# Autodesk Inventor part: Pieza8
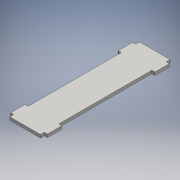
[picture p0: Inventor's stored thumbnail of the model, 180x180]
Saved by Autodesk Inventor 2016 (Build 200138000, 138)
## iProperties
Created: 2016-06
Part Number: Pieza8
Material: Genérico
Document SubType Name: Modeling
Designer: adm
Density: 1 g/cm^3
Appearance: Valor por defecto
Author: adm
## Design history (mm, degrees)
sketch "Boceto1"
  geometry: L1 (29.5, -125)-(-29.5, -125); L2 (-29.5, 125)-(29.5, 125); L3 (29.5, -125)-(-29.5, 125); L4 (-29.5, -125)-(29.5, 125); L5 (29.5, 117.561)-(35.5, 117.561); L6 (35.5, 117.561)-(35.5, 89.561); L7 (35.5, 89.561)-(29.5, 89.561); L8 (0, 0)-(-55.304, 0); L9 (0, 0)-(0, -42.823); L10 (-29.5, 117.561)-(-35.5, 117.561); L11 (-35.5, 117.561)-(-35.5, 89.561); L12 (-35.5, 89.561)-(-29.5, 89.561); L13 (35.5, -89.56)-(29.5, -89.56); L14 (35.5, -117.56)-(35.5, -89.56); L15 (29.5, -117.56)-(35.5, -117.56); L16 (-35.5, -89.561)-(-29.5, -89.561); L17 (-29.5, -117.561)-(-35.5, -117.561); L18 (-35.5, -117.561)-(-35.5, -89.561); L19 (29.5, -117.56)-(29.5, -125); L20 (-29.5, -125)-(-29.5, -117.561); L21 (-29.5, -89.561)-(-29.5, 89.561); L22 (-29.5, 117.561)-(-29.5, 125); L23 (29.5, 125)-(29.5, 117.561); L24 (29.5, 89.561)-(29.5, -89.56)
  constraints: 48 end point, 12 symmetric about line, 11 parallel, 4 perpendicular, 3 horizontal, 2 midpoint, 1 vertical
  dimensions: "d0" = 59 distance of L1.start L1.end; "d1" = 250 distance of L2.end L1.start; "d2" = 28 distance of L5.end L6.end; "d3" = 6 distance of L6.end L7.end; "d4" = 117.5605 distance from line of L5 L8.start
extrude "Extrusión1" new body sketch "Boceto1" distance "d5" = 6; taper "d6" = 0 deg
node "Sólido1"
